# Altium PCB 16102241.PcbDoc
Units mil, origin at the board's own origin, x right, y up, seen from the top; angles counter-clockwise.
Board outline 3200 x 2195 mil, 2 copper layers (Top Layer, Bottom Layer); 26 components, 17 nets, 64 pads, 0 vias.
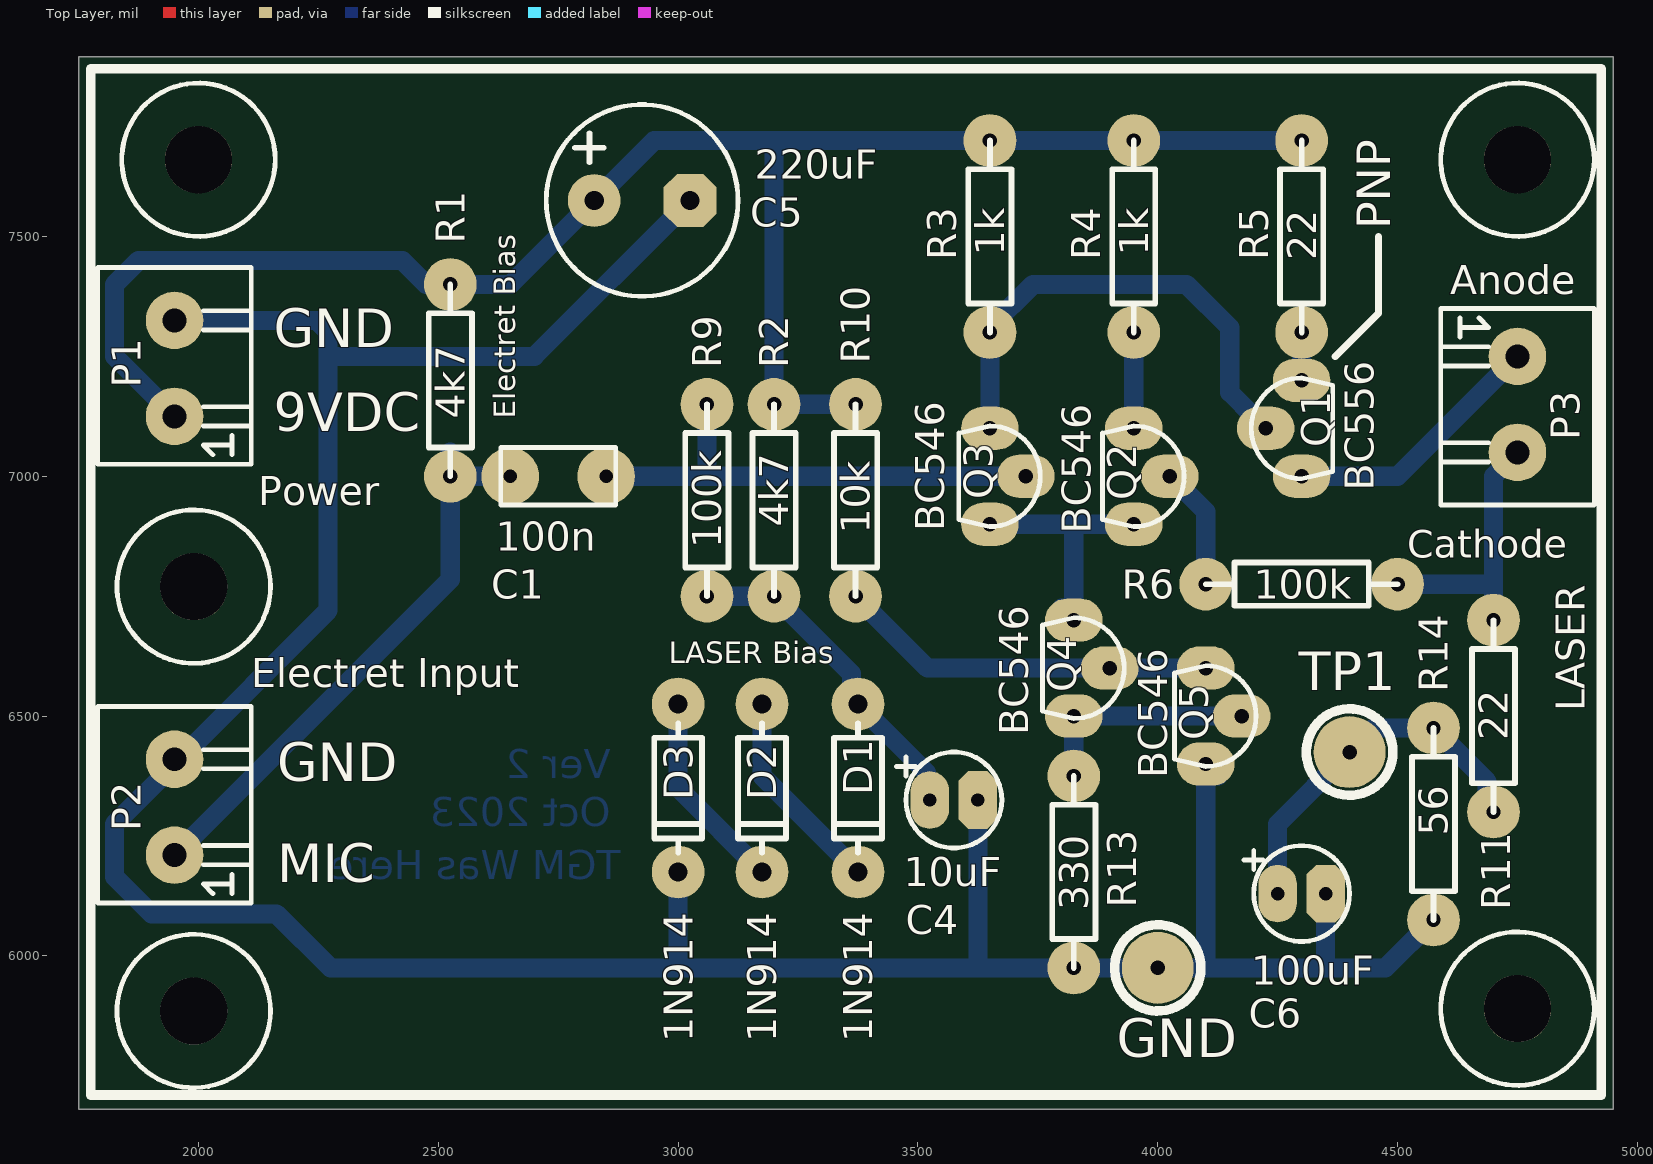
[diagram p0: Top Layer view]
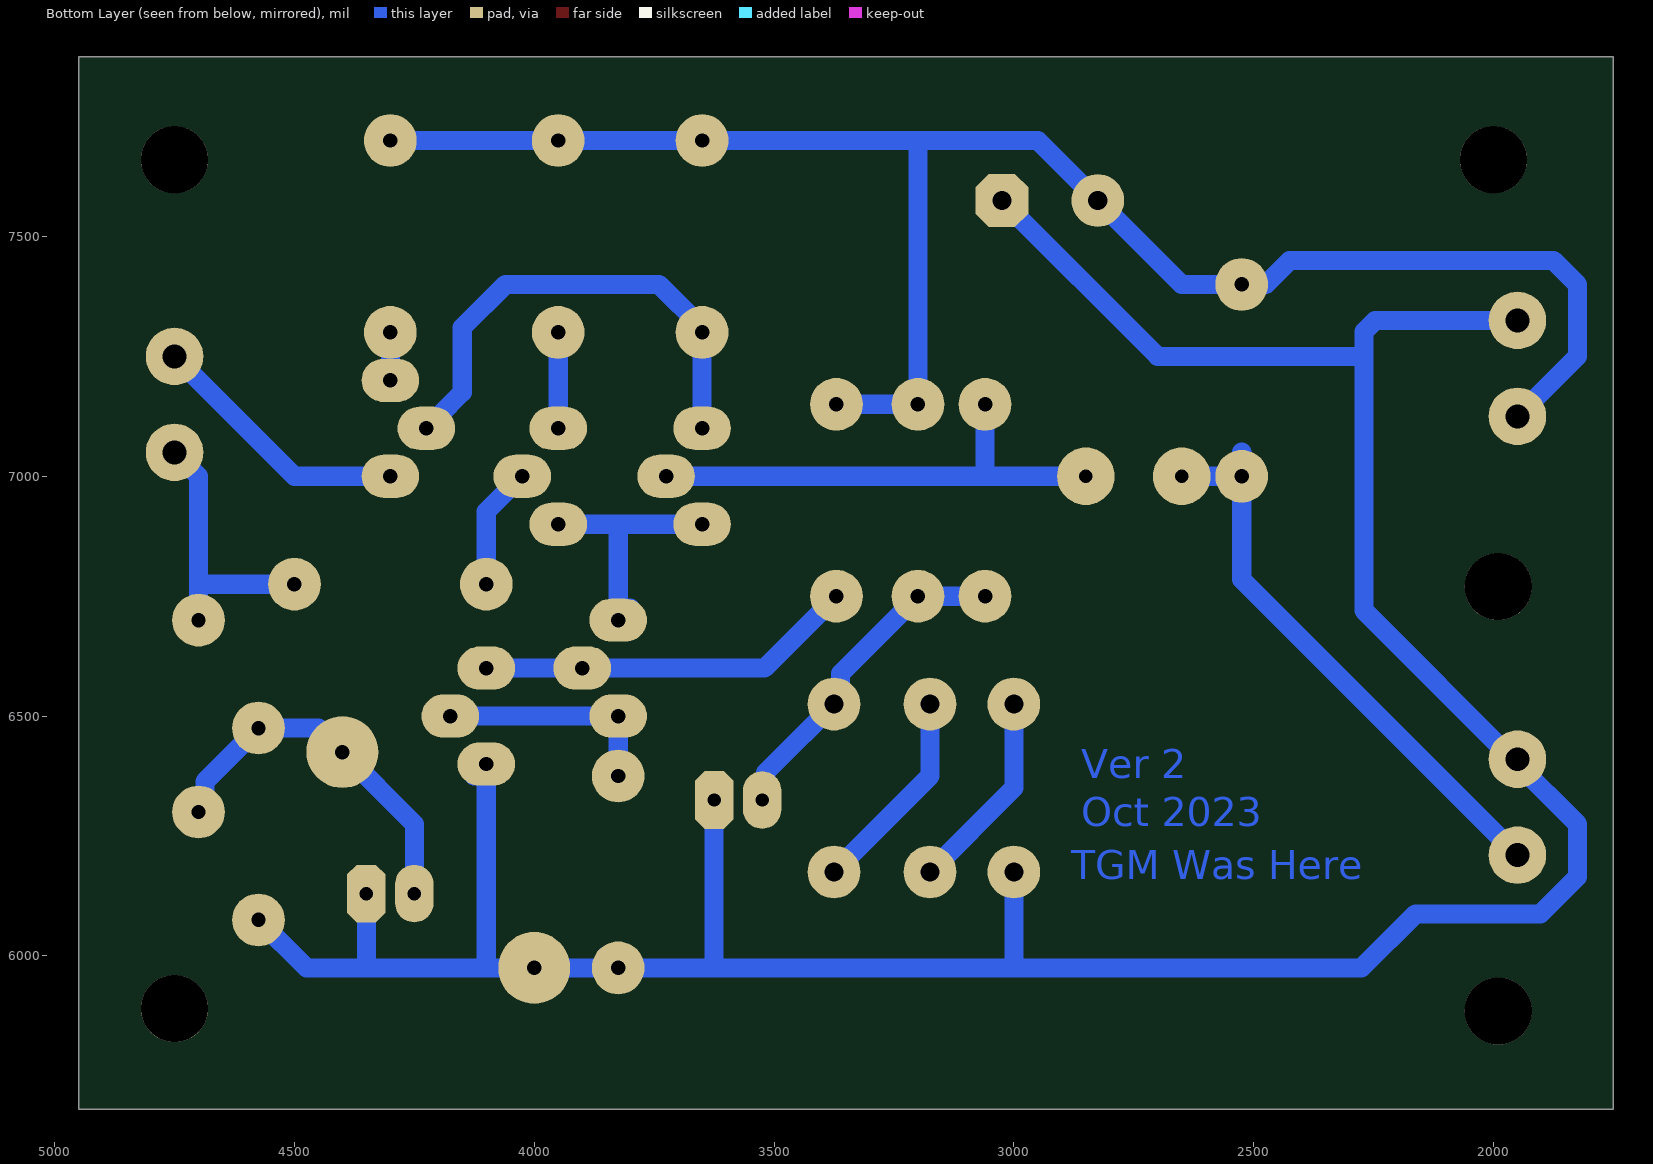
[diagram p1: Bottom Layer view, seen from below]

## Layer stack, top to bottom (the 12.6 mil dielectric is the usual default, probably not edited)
Top Solder: solder mask 0.4, Solder Resist, Dk 3.5
Top Layer: signal copper 1.4
Dielectric1: dielectric 12.6, FR-4, Dk 4.8
Bottom Layer: signal copper 1.4
Bottom Solder: solder mask 0.4, Solder Resist, Dk 3.5

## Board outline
1750,7875 4950,7875 4950,5680 1750,5680

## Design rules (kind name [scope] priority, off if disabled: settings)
Clearance Clearance_2 [HasFootprint('MSOP-12')] p1: gap=8 ignorepadtopadclearanceinfootprint=FALSE
Clearance Polygon_Clearance [(IsRegion)] p2: gap=15 ignorepadtopadclearanceinfootprint=FALSE
Clearance [IsPad] p3: gap=8 ignorepadtopadclearanceinfootprint=FALSE
Clearance bypass_Cap [(IsRegion) vs C64] p4: gap=15 ignorepadtopadclearanceinfootprint=FALSE
Clearance Clearance_1 [All] p5: gap=10 ignorepadtopadclearanceinfootprint=FALSE
ComponentClearance [All] p1: gap=5 collisioncheckmode=3 verticalgap=10 showdistances=FALSE
Height [All] p1: minheight=0 maxheight=2100 prefheight=500
HoleSize [All] p1: absolutevalues=TRUE maxlimit=200 minlimit=1 maxpercent=80.000 minpercent=20.000
PlaneConnect PlaneConnect_1 [C64] p1: pad.planeconnectstyle=Direct pad.reliefexpansion=20 pad.reliefentries=4 pad.reliefconductorwidth=10 pad.reliefairgap=10 via.planeconnectstyle=Relief via.reliefexpansion=20 via.reliefentries=4 via.reliefconductorwidth=10 via.reliefairgap=10
PlaneConnect [All] p2: planeconnectstyle=Relief reliefexpansion=20 reliefentries=4 reliefconductorwidth=10 reliefairgap=10
PolygonConnect PolygonConnect_5 [InComponent('L1')] p1: connectstyle=Direct reliefconductorwidth=10 reliefentries=4 polygonreliefangle="90 Angle" airgapwidth=10
PolygonConnect PolygonConnect_4 [InComponent('C26')] p2: connectstyle=Direct reliefconductorwidth=10 reliefentries=4 polygonreliefangle="90 Angle" airgapwidth=10
PolygonConnect PolygonConnect_3 [InNamedPolygon('NONET_L01_P047')] p3: connectstyle=Direct reliefconductorwidth=10 reliefentries=4 polygonreliefangle="90 Angle" airgapwidth=10
PolygonConnect PolygonConnect_2 [InComponent('U1')] p4: connectstyle=Direct reliefconductorwidth=10 reliefentries=4 polygonreliefangle="90 Angle" airgapwidth=10
PolygonConnect PolygonConnect_1 [InComponent('C64')] p5: connectstyle=Direct reliefconductorwidth=10 reliefentries=4 polygonreliefangle="90 Angle" airgapwidth=10
PolygonConnect [All] p6: connectstyle=Relief reliefconductorwidth=25 reliefentries=4 polygonreliefangle="90 Angle" airgapwidth=15
RoutingVias [All] p1: holewidth=28 width=50 viastyle="Through Hole" minholewidth=28 minwidth=50 maxholewidth=28 maxwidth=50
SilkToSolderMaskClearance SilkscreenOverComponentPads [IsPad] p1: minsilkscreentomaskgap=10 clearancetoexposedcopper=TRUE
SolderMaskExpansion [All] p1: expansion=4 istentingtop=FALSE
Width [All] p1: maxlimit=500 minlimit=10 preferedwidth=40
25 further rules are at their usual default settings.

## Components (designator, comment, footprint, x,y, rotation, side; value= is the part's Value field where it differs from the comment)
C1 "100n" AXIAL0.2-CAP 2850,7000 r180 top
C4 "10uF" RB.1/.2 3625,6325 r180 top
C5 "220uF" RB.2/.4 2825,7575 r180 top value=10uF
C6 "100uF" RB.1/.2 4350,6130 r180 top value=10uF
D1 "1N914" "DIODE0.35-TH - AK" 3375,6525 r270 top
D2 "1N914" "DIODE0.35-TH - AK" 3175,6525 r270 top
D3 "1N914" "DIODE0.35-TH - AK" 3000,6525 r270 top
P1 "Power" CON2_SCREW 1950,7125 r0 top
P2 "Electret Input" CON2_SCREW 1950,6210 r0 top
P3 "LASER" CON2_SCREW 4750,7250 r180 top
Q1 "BC556" TO-92-PP 4200,7100 r90 top
Q2 "BC546" TO-92-PP 4050,7000 r270 top
Q3 "BC546" TO-92-PP 3750,7000 r270 top
Q4 "BC546" TO-92-PP 3925,6600 r270 top
Q5 "BC546" TO-92-PP 4200,6500 r270 top
R1 "4k7" AXIAL0.4 2525,7400 r270 top
R2 "4k7" AXIAL0.4 3200,7150 r270 top
R3 "1k" AXIAL0.4 3650,7700 r270 top
R4 "1k" AXIAL0.4 3950,7700 r270 top
R5 "22" AXIAL0.4 4300,7700 r270 top
R6 "100k" AXIAL0.4 4100,6775 r0 top
R9 "100k" AXIAL0.4 3060,7150 r270 top
R10 "10k" AXIAL0.4 3370,7150 r270 top
R11 "22" AXIAL0.4 4700,6700 r270 top
R13 "330" AXIAL0.4 3825,6375 r270 top
R14 "56" AXIAL0.4 4575,6475 r270 top

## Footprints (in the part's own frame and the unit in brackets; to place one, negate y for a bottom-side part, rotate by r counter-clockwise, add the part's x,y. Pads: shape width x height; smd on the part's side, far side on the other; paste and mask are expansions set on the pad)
AXIAL0.2-CAP [mil]
  round 120 hole 28: 1(0,0) 2(200,0)
  silkscreen extent -20,-60 220,60, body extent -25,-65 225,65, height 200
AXIAL0.4 [mil] "resistor"
  round 110 hole 30: 1(0,0) 2(400,0)
  silkscreen extent 0,-45 400,45, body extent -5,-50 405,50, height 100
CON2_SCREW [mil]
  round 120 hole 50: 1(0,0) 2(0,200)
  silkscreen extent -160,-100 160,310, body extent -160,-100 160,310, height 301
"DIODE0.35-TH - AK" [mil] "DO-41 footprint"
  round 110 hole 40: A(0,0) K(350,0)
  silkscreen extent 40,-50 310,50, body extent -15,-55 365,55, height 110
RB.1/.2 [mil]
  oval 80x120 hole 28: 1(100,0)
  oct 80x120 hole 28: 2(0,0)
  silkscreen extent -50,-100 170,100, body extent -50,-100 150,100, height 400
RB.2/.4 [mil]
  round 110 hole 40: 1(0,0)
  oct 110x110 hole 40: 2(-200,0)
  silkscreen extent -300,-200 100,200, body extent -300,-200 100,200, height 1000
TO-92-PP [mil]
  oval 90x120 hole 30: B(0,-25) C(-100,-100) E(100,-100)
  silkscreen extent -105,-165 105,5, body extent -110,-165 110,5, height 500

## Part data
C1: library part Cap, "Altronics p/n R3025B"
C4: library part "Cap Pol1", "Altronics p/n R5065"
C5: library part "Cap Pol1", "Altronics p/n R5143"
C6: library part "Cap Pol1", "Altronics p/n R5123"
D1 D2 D3: library part DIODE, "Altroncs p/n Z0101"
P1 P2 P3: library part "Header 2", "Altronics p/n P2032B"
Q1: library part PNP, "Altronics p/n Z1052"
Q2 Q3 Q4 Q5: library part NPN, "Altronics p/n Z1039"
R1 R2: library part RES2, "Altronics p/n R7574"
R3 R4: library part RES2, "Altronics p/n R7558"
R5 R11: library part RES2, "Altronics p/n R7518"
R6 R9: library part RES2, "Altronics p/n R7606"
R10: library part RES2, "Altronics p/n R7582"
R13: library part RES2, "Altronics p/n R7546"
R14: library part RES2, "Altronics p/n R7528"

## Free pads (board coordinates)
  round 140 hole 140: 2(1990,5885) 2(1990,6770) 2(2000,7660) 2(4750,5890) 2(4750,7660)
  round 150 hole 30: 3(4000,5975) 4(4400,6425)

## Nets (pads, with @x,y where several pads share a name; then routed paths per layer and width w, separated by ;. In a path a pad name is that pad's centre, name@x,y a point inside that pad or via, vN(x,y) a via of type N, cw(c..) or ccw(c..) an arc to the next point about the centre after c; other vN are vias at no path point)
+9V: C5.1 P1.1 R1.1 R2.1 R3.1 R4.1 R5.1 R10.1 | length 3687.5
  Bottom Layer w40: P1.1 1825,7250 1825,7400 1875,7450 2425,7450 2475,7400 R1.1 2650,7400 C5.1 2950,7700 3200,7700 ; R10.1 R2.1 3200,7700 ; R5.1 R4.1 R3.1 3375,7700 3200,7700
GND: C4.2 C5.2 C6.2 D3.K P1.2 P2.2 pad.3 Q5.E R13.2 R14.2 | length 6611.9
  Bottom Layer w40: P1.2 2246.57,7325 2270,7301.57 2270,7250 ; D3.K 3000,5975 ; C5.2 2700,7250 2270,7250 ; C4.2 3625,5975 ; R13.2@3850,6000 R13.2 ; Q5.E@4125,6375 4124.57,6375.43 4124.57,6376.9 4101.47,6400 Q5.E 4100,5975 ; C6.2 4350,5975 ; R14.2 4475,5975 4350,5975 ; 2270,7250 2270,6720 1955,6405 1825,6275 1825,6165 1902.5,6087.5 2162.5,6087.5 2275,5975 3000,5975 ; 3000,5975 3625,5975 ; 3625,5975 R13.2 ; R13.2 pad.3 4100,5975 ; 4100,5975 4350,5975
NetC1_1: C1.1 Q3.B R9.1 | length 1025
  Bottom Layer w40: C1.1 3060,7000 ; R9.1 3060,7000 ; Q3.B 3060,7000
NetC1_2: C1.2 P2.1 R1.2 | length 1203.2
  Bottom Layer w40: P2.1 2525,6785 R1.2 ; R1.2@2525,7050 R1.2 ; C1.2 R1.2
NetC4_1: C4.1 D1.A R2.2 R9.2 | length 699.6
  Bottom Layer w40: R9.2 R2.2 3361.61,6588.39 3361.61,6538.39 3517.35,6382.65 3517.35,6332.65 C4.1
NetC6_1: C6.1 pad.4 R11.2 R14.1 | length 779.6
  Bottom Layer w40: C6.1 4250,6275 pad.4 4450,6475 R14.1 4686.61,6363.39 4686.61,6313.39 R11.2
NetD1_K: D1.K D2.A | length 432.8
  Bottom Layer w40: D2.A 3175,6375 D1.K
NetD2_K: D2.K D3.A | length 422.5
  Bottom Layer w40: D3.A 3000,6350 D2.K
NetP3_1: P3.1 Q1.C | length 553.6
  Bottom Layer w40: Q1.C 4500,7000 P3.1
NetP3_2: P3.2 R6.2 R11.1 | length 570.7
  Bottom Layer w40: R6.2 4700,6775 ; R11.1 4700,6775 ; P3.2 4700,7000 4700,6775
NetQ1_B: Q1.B Q3.C R3.2 | length 1026.5
  Bottom Layer w40: Q3.C 3650,7310 3740,7400 4060,7400 4150,7310 4150,7175 4200.43,7124.57 4200.43,7123.1 4223.53,7100 Q1.B
NetQ1_E: Q1.E R5.2 | length 100
  Bottom Layer w40: Q1.E R5.2
NetQ2_B: Q2.B R6.1 | length 256.9
  Bottom Layer w40: Q2.B 4026.47,7000 4100,6926.47 R6.1
NetQ2_C: Q2.C R4.2 | length 200
  Bottom Layer w40: Q2.C R4.2
NetQ2_E: Q2.E Q3.E Q4.C | length 535.4
  Bottom Layer w40: Q3.E 3825,6900 ; Q4.C@3800,6725 Q4.C 3825,6900 ; Q2.E 3825,6900
NetQ4_B: Q4.B Q5.C R10.2 | length 792.1
  Bottom Layer w40: R10.2 3520,6600 Q4.B Q5.C
NetQ4_E: Q4.E Q5.B R13.1 | length 475
  Bottom Layer w40: R13.1 Q4.E Q5.B

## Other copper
Bottom Layer:
  text "Ver 2" at 2860,6370 h60
  text "Oct 2023" at 2860,6270 h60
  text "TGM Was Here" at 2880,6160 h60

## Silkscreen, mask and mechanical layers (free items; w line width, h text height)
Top Overlay:
  circle w10: c1990,6770 r160
  circle w20: c4400,6425 r90.14
  circle w20: c4000,5975 r90
  circle w10: c4750,5890 r160
  circle w10: c4750,7660 r160
  circle w10: c1990,5885 r160
  circle w10: c2000,7660 r160
  lines w15: 4370,7250 4460,7340 4460,7400 4460,7500
  lines w20: 1775,5710 1775,7850 4925,7850 4925,5710 1775,5710
  text "PNP" at 4485,7515 h70 r90
  text "Anode" at 4610,7380 h60
  text "GND" at 2156.67,7269.24 h80
  text "Electret Bias" at 2660,7120 h45 r90
  text "9VDC" at 2156.67,7094.24 h80
  text "Cathode" at 4520,6830 h58
  text "LASER Bias" at 2980,6610 h45
  text "TP1" at 4294,6554 h80
  text "GND" at 2164,6364 h80
  text "MIC" at 2164,6154 h80
  text "GND" at 3914,5789 h80
Mechanical 1:
  lines w10: 1575,4300 6125,4300 6125,9525 1575,9525 1575,4300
